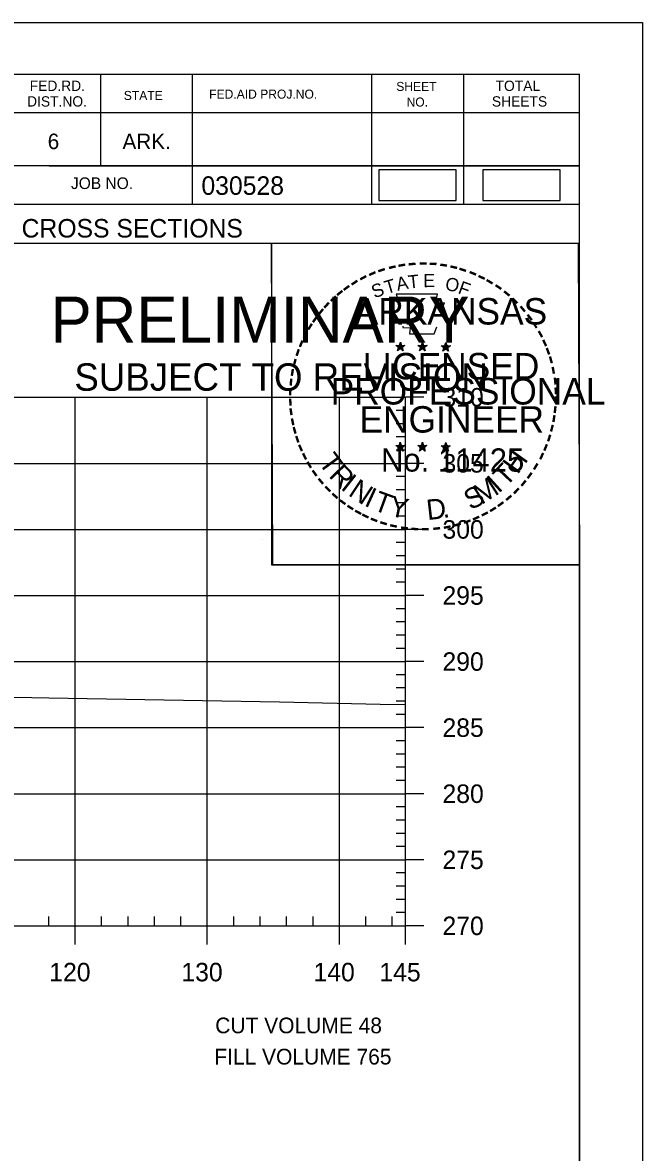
# Model space of a CAD drawing. Extents: x 1370843 to 1371177, y 380307 to 382654.
# Drawn here: x 1371129.7 to 1371176.6, y 381715.3 to 381800.8 of the extents above; entities that cross this region are included whole.
import ezdxf

# ---------------------------------------------------------------- set-up
doc = ezdxf.new("R2010")
doc.units = 0
for name, color, linetype in [('R_Axis', 7, 'Continuous'), ('R_Axis Annot', 7, 'Continuous'), ('R_Border', 7, 'Continuous'), ('R_Border Notes', 7, 'Continuous'), ('R_Border PE', 7, 'Continuous'), ('R_Border Prem', 7, 'Continuous'), ('R_Draft', 7, 'Continuous'), ('R_Exist Surface', 7, 'Continuous'), ('R_Grid', 7, 'Continuous'), ('R_No Plot', 7, 'Continuous')]:
    doc.layers.add(name, color=color, linetype=linetype)

msp = doc.modelspace()

# ---------------------------------------------------------------- linework, layer by layer
at = {"layer": 'R_Axis'}
for p, q in [((1371158.709, 381732.476), (1371158.709, 381772.476)), ((1371160.109, 381772.476), (1371158.709, 381772.476)), ((1371158.709, 381771.476), (1371158.009, 381771.476)), ((1371158.709, 381770.476), (1371158.009, 381770.476)), ((1371158.709, 381769.476), (1371158.009, 381769.476)), ((1371158.709, 381768.476), (1371158.009, 381768.476)), ((1371160.109, 381767.476), (1371158.709, 381767.476)), ((1371158.709, 381766.476), (1371158.009, 381766.476)), ((1371158.709, 381765.476), (1371158.009, 381765.476)), ((1371158.709, 381764.476), (1371158.009, 381764.476)), ((1371158.709, 381763.476), (1371158.009, 381763.476)), ((1371160.109, 381762.476), (1371158.709, 381762.476)), ((1371158.709, 381761.476), (1371158.009, 381761.476)), ((1371158.709, 381760.476), (1371158.009, 381760.476)), ((1371158.709, 381759.476), (1371158.009, 381759.476)), ((1371158.709, 381758.476), (1371158.009, 381758.476)), ((1371160.109, 381757.476), (1371158.709, 381757.476)), ((1371158.709, 381756.476), (1371158.009, 381756.476)), ((1371158.709, 381755.476), (1371158.009, 381755.476)), ((1371158.709, 381754.476), (1371158.009, 381754.476)), ((1371158.709, 381753.476), (1371158.009, 381753.476)), ((1371160.109, 381752.476), (1371158.709, 381752.476)), ((1371158.709, 381751.476), (1371158.009, 381751.476)), ((1371158.709, 381750.476), (1371158.009, 381750.476)), ((1371158.709, 381749.476), (1371158.009, 381749.476)), ((1371158.709, 381748.476), (1371158.009, 381748.476)), ((1371160.109, 381747.476), (1371158.709, 381747.476)), ((1371158.709, 381746.476), (1371158.009, 381746.476)), ((1371158.709, 381745.476), (1371158.009, 381745.476)), ((1371158.709, 381744.476), (1371158.009, 381744.476)), ((1371158.709, 381743.476), (1371158.009, 381743.476)), ((1371160.109, 381742.476), (1371158.709, 381742.476)), ((1371158.709, 381741.476), (1371158.009, 381741.476)), ((1371158.709, 381740.476), (1371158.009, 381740.476)), ((1371158.709, 381739.476), (1371158.009, 381739.476)), ((1371158.709, 381738.476), (1371158.009, 381738.476)), ((1371160.109, 381737.476), (1371158.709, 381737.476)), ((1371158.709, 381736.476), (1371158.009, 381736.476)), ((1371158.709, 381735.476), (1371158.009, 381735.476)), ((1371158.709, 381734.476), (1371158.009, 381734.476)), ((1371131.709, 381732.476), (1371131.709, 381733.176)), ((1371135.709, 381732.476), (1371135.709, 381733.176)), ((1371137.709, 381732.476), (1371137.709, 381733.176)), ((1371139.709, 381732.476), (1371139.709, 381733.176)), ((1371141.709, 381732.476), (1371141.709, 381733.176)), ((1371145.709, 381732.476), (1371145.709, 381733.176)), ((1371147.709, 381732.476), (1371147.709, 381733.176)), ((1371149.709, 381732.476), (1371149.709, 381733.176)), ((1371151.709, 381732.476), (1371151.709, 381733.176)), ((1371155.709, 381732.476), (1371155.709, 381733.176)), ((1371157.709, 381732.476), (1371157.709, 381733.176)), ((1371158.709, 381733.476), (1371158.009, 381733.476)), ((1370868.709, 381732.476), (1371158.709, 381732.476)), ((1371133.709, 381731.076), (1371133.709, 381732.476)), ((1371143.709, 381731.076), (1371143.709, 381732.476)), ((1371153.709, 381731.076), (1371153.709, 381732.476)), ((1371158.709, 381731.076), (1371158.709, 381732.476)), ((1371160.109, 381732.476), (1371158.709, 381732.476))]:
    msp.add_line(p, q, dxfattribs=at)
at = {"layer": 'R_Border'}
for p, q in [((1370855.709, 381796.936), (1371171.889, 381796.936)), ((1371135.629, 381796.936), (1371135.629, 381789.996)), ((1371142.569, 381796.936), (1371142.569, 381787.056)), ((1371156.149, 381796.936), (1371156.149, 381787.056)), ((1371163.089, 381796.936), (1371163.089, 381787.056)), ((1371171.889, 381591.476), (1371171.889, 381796.936)), ((1371171.889, 381793.996), (1371128.789, 381793.996)), ((1371171.889, 381794.016), (1371171.889, 381794.016)), ((1371171.889, 381789.996), (1371128.789, 381789.996)), ((1371131.749, 381789.996), (1371171.889, 381789.996)), ((1371171.889, 381787.056), (1371089.629, 381787.056)), ((1371128.789, 381784.136), (1371171.889, 381784.136))]:
    msp.add_line(p, q, dxfattribs=at)
at = {"layer": 'R_Border PE'}
for p, q in [((1371158.323, 381776.645), (1371158.282, 381776.393)), ((1371158.323, 381776.28), (1371158.323, 381776.645)), ((1371158.323, 381776.645), (1371158.372, 381776.395)), ((1371159.993, 381776.645), (1371159.952, 381776.393)), ((1371159.993, 381776.28), (1371159.993, 381776.645)), ((1371159.993, 381776.645), (1371160.042, 381776.395)), ((1371161.757, 381776.633), (1371161.716, 381776.381)), ((1371161.757, 381776.268), (1371161.757, 381776.633)), ((1371161.757, 381776.633), (1371161.806, 381776.383)), ((1371157.974, 381776.391), (1371158.323, 381776.28)), ((1371157.974, 381776.391), (1371158.227, 381776.346)), ((1371157.974, 381776.391), (1371158.211, 381776.269)), ((1371158.107, 381775.983), (1371158.323, 381776.28)), ((1371158.107, 381775.983), (1371158.233, 381776.227)), ((1371158.107, 381775.983), (1371158.321, 381776.2)), ((1371158.536, 381775.983), (1371158.321, 381776.197)), ((1371158.67, 381776.391), (1371158.323, 381776.28)), ((1371158.536, 381775.983), (1371158.323, 381776.28)), ((1371158.67, 381776.391), (1371158.384, 381776.342)), ((1371158.536, 381775.983), (1371158.399, 381776.274)), ((1371158.67, 381776.391), (1371158.466, 381776.289)), ((1371159.644, 381776.391), (1371159.993, 381776.28)), ((1371159.644, 381776.391), (1371159.897, 381776.346)), ((1371159.644, 381776.391), (1371159.881, 381776.269)), ((1371159.777, 381775.983), (1371159.993, 381776.28)), ((1371159.777, 381775.983), (1371159.903, 381776.227)), ((1371159.777, 381775.983), (1371159.991, 381776.2)), ((1371160.206, 381775.983), (1371159.991, 381776.197)), ((1371160.34, 381776.391), (1371159.993, 381776.28)), ((1371160.206, 381775.983), (1371159.993, 381776.28)), ((1371160.34, 381776.391), (1371160.054, 381776.342)), ((1371160.206, 381775.983), (1371160.069, 381776.274)), ((1371160.34, 381776.391), (1371160.136, 381776.289)), ((1371161.408, 381776.379), (1371161.757, 381776.268)), ((1371161.408, 381776.379), (1371161.661, 381776.334)), ((1371161.408, 381776.379), (1371161.645, 381776.257)), ((1371161.541, 381775.971), (1371161.757, 381776.268)), ((1371161.541, 381775.971), (1371161.667, 381776.215)), ((1371161.541, 381775.971), (1371161.755, 381776.188)), ((1371161.97, 381775.971), (1371161.755, 381776.185)), ((1371162.104, 381776.379), (1371161.757, 381776.268)), ((1371161.97, 381775.971), (1371161.757, 381776.268)), ((1371162.104, 381776.379), (1371161.818, 381776.33)), ((1371161.97, 381775.971), (1371161.833, 381776.262)), ((1371162.104, 381776.379), (1371161.9, 381776.277)), ((1371157.97, 381768.818), (1371158.319, 381768.707)), ((1371157.97, 381768.818), (1371158.223, 381768.773)), ((1371157.97, 381768.818), (1371158.207, 381768.696)), ((1371158.319, 381769.072), (1371158.278, 381768.82)), ((1371158.319, 381768.707), (1371158.319, 381769.072)), ((1371158.319, 381769.072), (1371158.368, 381768.822)), ((1371158.666, 381768.818), (1371158.319, 381768.707)), ((1371158.666, 381768.818), (1371158.38, 381768.769)), ((1371158.666, 381768.818), (1371158.462, 381768.716)), ((1371159.639, 381768.818), (1371159.988, 381768.707)), ((1371159.639, 381768.818), (1371159.892, 381768.773)), ((1371159.639, 381768.818), (1371159.876, 381768.696)), ((1371159.988, 381769.072), (1371159.947, 381768.82)), ((1371159.988, 381768.707), (1371159.988, 381769.072)), ((1371159.988, 381769.072), (1371160.037, 381768.822)), ((1371160.335, 381768.818), (1371159.988, 381768.707)), ((1371160.335, 381768.818), (1371160.049, 381768.769)), ((1371160.335, 381768.818), (1371160.131, 381768.716)), ((1371161.406, 381768.808), (1371161.755, 381768.697)), ((1371161.406, 381768.808), (1371161.659, 381768.763)), ((1371161.406, 381768.808), (1371161.643, 381768.686)), ((1371161.755, 381769.062), (1371161.714, 381768.81)), ((1371161.755, 381768.697), (1371161.755, 381769.062)), ((1371161.755, 381769.062), (1371161.804, 381768.812)), ((1371162.102, 381768.808), (1371161.755, 381768.697)), ((1371162.102, 381768.808), (1371161.816, 381768.759)), ((1371162.102, 381768.808), (1371161.898, 381768.706)), ((1371158.103, 381768.41), (1371158.319, 381768.707)), ((1371158.103, 381768.41), (1371158.229, 381768.654)), ((1371158.103, 381768.41), (1371158.317, 381768.627)), ((1371158.532, 381768.41), (1371158.317, 381768.624)), ((1371158.532, 381768.41), (1371158.319, 381768.707)), ((1371158.532, 381768.41), (1371158.395, 381768.701)), ((1371159.772, 381768.41), (1371159.988, 381768.707)), ((1371159.772, 381768.41), (1371159.898, 381768.654)), ((1371159.772, 381768.41), (1371159.986, 381768.627)), ((1371160.201, 381768.41), (1371159.986, 381768.624)), ((1371160.201, 381768.41), (1371159.988, 381768.707)), ((1371160.201, 381768.41), (1371160.064, 381768.701)), ((1371161.539, 381768.4), (1371161.755, 381768.697)), ((1371161.539, 381768.4), (1371161.665, 381768.644)), ((1371161.539, 381768.4), (1371161.753, 381768.617)), ((1371161.968, 381768.4), (1371161.753, 381768.614)), ((1371161.968, 381768.4), (1371161.755, 381768.697)), ((1371161.968, 381768.4), (1371161.831, 381768.691))]:
    msp.add_line(p, q, dxfattribs=at)
for points in [[(1371158.015, 381780.269), (1371158.284, 381779.442)], [(1371161.526, 381779.347), (1371161.668, 381779.631), (1371160.983, 381779.607), (1371161.131, 381780.269), (1371158.015, 381780.269)], [(1371158.507, 381777.846), (1371158.507, 381777.759), (1371159.07, 381777.74), (1371159.016, 381777.267), (1371160.886, 381777.267), (1371161.087, 381777.803)], [(1371158.323, 381776.645), (1371158.536, 381775.983), (1371157.974, 381776.391), (1371158.67, 381776.391), (1371158.107, 381775.983), (1371158.323, 381776.645)], [(1371159.993, 381776.645), (1371160.206, 381775.983), (1371159.644, 381776.391), (1371160.34, 381776.391), (1371159.777, 381775.983), (1371159.993, 381776.645)], [(1371161.757, 381776.633), (1371161.97, 381775.971), (1371161.408, 381776.379), (1371162.104, 381776.379), (1371161.541, 381775.971), (1371161.757, 381776.633)], [(1371158.319, 381769.072), (1371158.532, 381768.41), (1371157.97, 381768.818), (1371158.666, 381768.818), (1371158.103, 381768.41), (1371158.319, 381769.072)], [(1371159.988, 381769.072), (1371160.201, 381768.41), (1371159.639, 381768.818), (1371160.335, 381768.818), (1371159.772, 381768.41), (1371159.988, 381769.072)], [(1371161.755, 381769.062), (1371161.968, 381768.4), (1371161.406, 381768.808), (1371162.102, 381768.808), (1371161.539, 381768.4), (1371161.755, 381769.062)]]:
    msp.add_lwpolyline(points, dxfattribs=at)
for centre, radius in [((1371158.322, 381776.279), 0.172), ((1371158.322, 381776.279), 0.145), ((1371158.322, 381776.279), 0.116), ((1371158.322, 381776.279), 0.0991), ((1371158.322, 381776.279), 0.0747), ((1371158.322, 381776.279), 0.0495), ((1371158.322, 381776.279), 0.0296), ((1371159.992, 381776.279), 0.172), ((1371159.992, 381776.279), 0.145), ((1371159.992, 381776.279), 0.116), ((1371159.992, 381776.279), 0.0991), ((1371159.992, 381776.279), 0.0747), ((1371159.992, 381776.279), 0.0495), ((1371159.992, 381776.279), 0.0296), ((1371161.756, 381776.267), 0.172), ((1371161.756, 381776.267), 0.145), ((1371161.756, 381776.267), 0.116), ((1371161.756, 381776.267), 0.0991), ((1371161.756, 381776.267), 0.0747), ((1371161.756, 381776.267), 0.0495), ((1371161.756, 381776.267), 0.0296), ((1371158.318, 381768.706), 0.172), ((1371158.318, 381768.706), 0.145), ((1371158.318, 381768.706), 0.116), ((1371158.318, 381768.706), 0.0991), ((1371158.318, 381768.706), 0.0747), ((1371159.987, 381768.706), 0.172), ((1371159.987, 381768.706), 0.145), ((1371159.987, 381768.706), 0.116), ((1371159.987, 381768.706), 0.0991), ((1371159.987, 381768.706), 0.0747), ((1371161.754, 381768.696), 0.172), ((1371161.754, 381768.696), 0.145), ((1371161.754, 381768.696), 0.116), ((1371161.754, 381768.696), 0.0991), ((1371161.754, 381768.696), 0.0747), ((1371158.318, 381768.706), 0.0495), ((1371158.318, 381768.706), 0.0296), ((1371159.987, 381768.706), 0.0495), ((1371159.987, 381768.706), 0.0296), ((1371161.754, 381768.696), 0.0495), ((1371161.754, 381768.696), 0.0296)]:
    msp.add_circle(centre, radius, dxfattribs=at)
at = {"layer": 'R_Draft'}
for points in [[(1371156.702, 381787.371), (1371162.536, 381787.371), (1371162.536, 381789.681), (1371156.702, 381789.681)], [(1371164.572, 381787.371), (1371170.406, 381787.371), (1371170.406, 381789.681), (1371164.572, 381789.681)]]:
    msp.add_lwpolyline(points, close=True, dxfattribs=at)
at = {"layer": 'R_Exist Surface'}
msp.add_lwpolyline([(1371082.984, 381744.028), (1371094.92, 381744.343), (1371105.544, 381744.371), (1371112.113, 381744.479), (1371117.256, 381744.501), (1371121.786, 381747.246), (1371126.243, 381749.812), (1371130.437, 381749.748), (1371131.72, 381749.721), (1371149.166, 381749.431), (1371156.796, 381749.259), (1371158.709, 381749.214)], dxfattribs=at)
at = {"layer": 'R_Grid'}
for p, q in [((1370868.709, 381772.476), (1371158.709, 381772.476)), ((1371133.709, 381732.476), (1371133.709, 381772.476)), ((1371143.709, 381732.476), (1371143.709, 381772.476)), ((1371153.709, 381732.476), (1371153.709, 381772.476)), ((1371158.709, 381732.476), (1371158.709, 381772.476)), ((1370868.709, 381767.476), (1371158.709, 381767.476)), ((1370868.709, 381762.476), (1371158.709, 381762.476)), ((1370868.709, 381757.476), (1371158.709, 381757.476)), ((1370868.709, 381752.476), (1371158.709, 381752.476)), ((1370868.709, 381747.476), (1371158.709, 381747.476)), ((1370868.709, 381742.476), (1371158.709, 381742.476)), ((1370868.709, 381737.476), (1371158.709, 381737.476)), ((1370868.709, 381732.476), (1371158.709, 381732.476))]:
    msp.add_line(p, q, dxfattribs=at)
at = {"layer": 'R_No Plot'}
for p, q in [((1370843.308, 381800.831), (1371176.642, 381800.831)), ((1371147.923, 381761.681), (1371147.923, 381761.681))]:
    msp.add_line(p, q, dxfattribs=at)
for points in [[(1370843.302, 381800.831), (1371176.642, 381800.831), (1371176.642, 381587.493), (1370843.302, 381587.493)], [(1371089.629, 381796.936), (1371089.629, 381787.056), (1371125.361, 381787.056), (1371125.361, 381784.136), (1371148.561, 381784.136), (1371148.561, 381759.804), (1371171.889, 381759.804), (1371171.889, 381591.476), (1370855.709, 381591.476), (1370855.709, 381796.936)], [(1371148.561, 381784.136), (1371171.768, 381784.136), (1371171.889, 381759.804), (1371148.681, 381759.804)]]:
    msp.add_lwpolyline(points, close=True, dxfattribs=at)

# ---------------------------------------------------------------- texts
at = {"layer": 'R_Axis Annot'}
for s, p in [('310', (1371161.509, 381771.776)), ('305', (1371161.509, 381766.776)), ('300', (1371161.509, 381761.776)), ('295', (1371161.509, 381756.776)), ('290', (1371161.509, 381751.776)), ('285', (1371161.509, 381746.776)), ('280', (1371161.509, 381741.776)), ('275', (1371161.509, 381736.776)), ('270', (1371161.509, 381731.776)), ('120', (1371131.748, 381728.276)), ('130', (1371141.748, 381728.276)), ('140', (1371151.748, 381728.276)), ('145', (1371156.735, 381728.276))]:
    msp.add_text(s, height=1.4, dxfattribs=at).set_placement(p)
at = {"layer": 'R_Border'}
for s, height, p in [('FED.RD.', 0.7819, (1371130.269, 381795.656)), ('SHEET', 0.684, (1371158.009, 381795.656)), ('TOTAL', 0.7819, (1371165.529, 381795.656)), ('STATE', 0.684, (1371137.389, 381794.976)), ('FED.AID PROJ.NO.', 0.684, (1371143.849, 381795.076)), ('DIST.NO.', 0.7819, (1371130.069, 381794.476)), ('NO.', 0.684, (1371158.789, 381794.476)), ('SHEETS', 0.7819, (1371165.249, 381794.476)), ('6', 1.172, (1371131.629, 381791.256)), ('ARK.', 1.1723, (1371137.289, 381791.256)), ('JOB NO.', 0.8792, (1371133.389, 381788.236)), ('030528', 1.4, (1371143.265, 381787.796)), ('CROSS SECTIONS', 1.4, (1371129.653, 381784.566))]:
    msp.add_text(s, height=height, rotation=360, dxfattribs=at).set_placement(p)
at = {"layer": 'R_Border Notes'}
for s, p in [('CUT VOLUME 48', (1371144.31, 381724.345)), ('FILL VOLUME 765', (1371144.235, 381721.982))]:
    msp.add_text(s, height=1.18747, dxfattribs=at).set_placement(p)
at = {"layer": 'R_Border PE'}
for s, height, rotation, p in [('-', 1.6, 13.63015, (1371157.513, 381781.637)), ('-', 1.6, 10.21935, (1371158.191, 381781.799)), ('-', 1.6, 5.89682, (1371158.92, 381781.909)), ('-', 1.6, 0.18623, (1371159.692, 381781.981)), ('-', 1.6, 357.74304, (1371160.415, 381781.968)), ('-', 1.6, 352.16172, (1371161.159, 381781.912)), ('-', 1.6, 347.20489, (1371161.878, 381781.798)), ('-', 1.6, 28.79182, (1371155.496, 381780.81)), ('-', 1.6, 24.30721, (1371156.129, 381781.127)), ('-', 1.6, 19.17608, (1371156.763, 381781.396)), ('A', 1, 11.21318, (1371158.11, 381780.529)), ('T', 1, 6.02276, (1371158.959, 381780.695)), ('E', 1, 0.83234, (1371160.064, 381780.805)), ('-', 1.6, 342.3362, (1371162.513, 381781.643)), ('-', 1.6, 337.85509, (1371163.248, 381781.42)), ('-', 1.6, 334.12109, (1371163.879, 381781.149)), ('-', 1.6, 36.23174, (1371154.321, 381780.045)), ('-', 1.6, 34.06357, (1371154.899, 381780.44)), ('S', 1, 21.59401, (1371156.37, 381779.947)), ('T', 1, 16.4036, (1371157.284, 381780.278)), ('O', 1, 350.4515, (1371161.668, 381780.595)), ('F', 1, 340.07066, (1371162.622, 381780.367)), ('-', 1.6, 329.64089, (1371164.458, 381780.866)), ('-', 1.6, 325.86266, (1371165.101, 381780.505)), ('-', 1.6, 42.96224, (1371153.412, 381779.25)), ('-', 1.6, 38.95066, (1371153.845, 381779.667)), ('ARKANSAS', 2, 360, (1371154.868, 381777.981)), ('-', 1.6, 320.52971, (1371165.711, 381780.079)), ('-', 1.6, 315.57859, (1371166.31, 381779.591)), ('-', 1.6, 50.61417, (1371152.561, 381778.286)), ('-', 1.6, 48.42305, (1371152.964, 381778.772)), ('-', 1.6, 309.87973, (1371166.879, 381779.041)), ('-', 1.6, 54.23247, (1371152.148, 381777.719)), ('-', 1.6, 306.65218, (1371167.404, 381778.439)), ('-', 1.6, 62.87135, (1371151.51, 381776.578)), ('-', 1.6, 58.07063, (1371151.823, 381777.192)), ('-', 1.4, 303.67529, (1371167.89, 381777.871)), ('-', 1.6, 299.66835, (1371168.209, 381777.264)), ('-', 1.6, 67.77427, (1371151.251, 381775.967)), ('-', 1.6, 294.66279, (1371168.533, 381776.652)), ('-', 1.6, 72.39447, (1371151.032, 381775.337)), ('LICENSED', 2, 360, (1371155.465, 381773.832)), ('DWB', 0.01, 360, (1371158.31, 381776.275)), ('DWB', 0.01, 360, (1371159.98, 381776.275)), ('DWB', 0.01, 360, (1371161.744, 381776.264)), ('-', 1.6, 290.57283, (1371168.79, 381776.075)), ('-', 1.6, 75.46096, (1371150.835, 381774.623)), ('-', 1.6, 285.12326, (1371169.024, 381775.495)), ('-', 1.6, 280.54934, (1371169.224, 381774.753)), ('-', 1.6, 81.20126, (1371150.703, 381773.91)), ('PROFESSIONAL', 2, 360, (1371153.042, 381771.928)), ('-', 1.6, 276.59616, (1371169.386, 381773.985)), ('-', 1.6, 89.06224, (1371150.602, 381772.518)), ('-', 1.6, 85.18634, (1371150.627, 381773.219)), ('-', 1.6, 274.33011, (1371169.446, 381773.263)), ('-', 1.6, 94.19588, (1371150.637, 381771.793)), ('-', 1.6, 269.94067, (1371169.48, 381772.631)), ('-', 1.6, 98.94793, (1371150.709, 381771.126)), ('ENGINEER', 2, 360, (1371155.229, 381769.803)), ('-', 1.6, 263.5172, (1371169.461, 381771.965)), ('-', 1.6, 101.71495, (1371150.844, 381770.393)), ('-', 1.6, 260.99529, (1371169.39, 381771.311)), ('-', 1.6, 105.45785, (1371151.006, 381769.798)), ('-', 1.6, 252.86809, (1371169.099, 381769.913)), ('-', 1.6, 255.7626, (1371169.28, 381770.633)), ('-', 1.6, 109.08742, (1371151.221, 381769.167)), ('-', 1.6, 114.06432, (1371151.475, 381768.571)), ('-', 1.6, 247.88866, (1371168.876, 381769.24)), ('-', 1.6, 115.72885, (1371151.78, 381767.953)), ('T', 1.54, 306.04056, (1371152.078, 381767.545)), ('No. 11425', 1.757, 360, (1371156.856, 381766.852)), ('DWB', 0.01, 360, (1371158.306, 381768.702)), ('DWB', 0.01, 360, (1371159.975, 381768.702)), ('DWB', 0.01, 360, (1371161.742, 381768.692)), ('H', 1.54, 54.60883, (1371167.199, 381766.581)), ('-', 1.6, 244.61971, (1371168.614, 381768.611)), ('-', 1.6, 120.44712, (1371152.137, 381767.367)), ('R', 1.54, 314.00497, (1371152.841, 381766.498)), ('T', 1.54, 46.64442, (1371166.309, 381765.638)), ('-', 1.6, 239.07125, (1371168.22, 381767.859)), ('-', 1.6, 125.89344, (1371152.54, 381766.806)), ('-', 1.6, 130.71812, (1371153.002, 381766.254)), ('I', 1.54, 321.96938, (1371153.741, 381765.566)), ('N', 1.54, 326.50021, (1371154.309, 381765.094)), ('M', 1.54, 32.65632, (1371164.463, 381764.313)), ('I', 1.54, 42.11359, (1371165.747, 381765.16)), ('-', 1.6, 231.25377, (1371167.388, 381766.64)), ('-', 1.6, 233.84524, (1371167.818, 381767.206)), ('-', 1.6, 134.22381, (1371153.519, 381765.709)), ('I', 1.54, 335.36034, (1371155.517, 381764.308)), ('T', 1.54, 339.89117, (1371156.178, 381763.981)), ('S', 1.54, 26.9312, (1371163.624, 381763.907)), ('-', 1.6, 225.76533, (1371166.909, 381766.076)), ('-', 1.6, 138.93382, (1371154.044, 381765.245)), ('-', 1.6, 144.64634, (1371154.6, 381764.839)), ('Y', 1.54, 347.85558, (1371157.395, 381763.535)), ('D', 1.54, 6.39691, (1371160.38, 381763.177)), ('-', 1.6, 215.73633, (1371165.838, 381765.095)), ('-', 1.6, 221.08509, (1371166.387, 381765.567)), ('-', 1.6, 148.08978, (1371155.161, 381764.468)), ('-', 1.6, 151.57039, (1371155.74, 381764.143)), ('-', 1.6, 154.60019, (1371156.262, 381763.896)), ('-', 1.6, 207.35684, (1371164.746, 381764.362)), ('-', 1.6, 212.24909, (1371165.304, 381764.708)), ('-', 1.6, 158.56121, (1371156.886, 381763.642)), ('-', 1.6, 162.79826, (1371157.573, 381763.429)), ('-', 1.6, 167.55551, (1371158.288, 381763.265)), ('-', 1.6, 191.28576, (1371162.097, 381763.329)), ('.', 1.54, 13.76417, (1371161.572, 381763.304)), ('-', 1.6, 195.47429, (1371162.826, 381763.528)), ('-', 1.6, 200.71842, (1371163.503, 381763.77)), ('-', 1.6, 204.25161, (1371164.122, 381764.043)), ('-', 1.6, 173.11546, (1371159.06, 381763.155)), ('-', 1.6, 176.51827, (1371159.808, 381763.102)), ('-', 1.6, 181.59176, (1371160.552, 381763.121)), ('-', 1.6, 185.81666, (1371161.361, 381763.197))]:
    msp.add_text(s, height=height, rotation=rotation, dxfattribs=at).set_placement(p)
at = {"layer": 'R_Border Prem'}
for s, height, p in [('PRELIMINARY', 3.5, (1371131.84, 381776.599)), ('DWB', 0.01, (1371132.587, 381778.448)), ('SUBJECT TO REVISION', 2.07511, (1371133.649, 381772.97))]:
    msp.add_text(s, height=height, rotation=360, dxfattribs=at).set_placement(p)

doc.saveas('drawing.dxf')
